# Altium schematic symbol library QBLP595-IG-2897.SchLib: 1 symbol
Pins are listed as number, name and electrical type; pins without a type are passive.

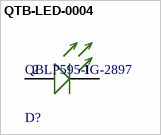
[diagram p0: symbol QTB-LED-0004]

## QTB-LED-0004
designator D?, comment QBLP595-IG-2897
LED GREEN CLEAR 0402 SMD; Manufacturer: QT Brightek (QTB); Luminous Intensity: 640mcd; Viewing Angle: 140°; Forward Voltage: 3.1V; Test Current: 20mA; Dominant Wavelength: 520nm; Lens Style: Flat; Lens Color: Colorless; Lens Size: 0.5mm
footprint FP-QBLP595-IG-2897-MFG
pins: 1 CATHODE (-), 2 ANODE (+)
